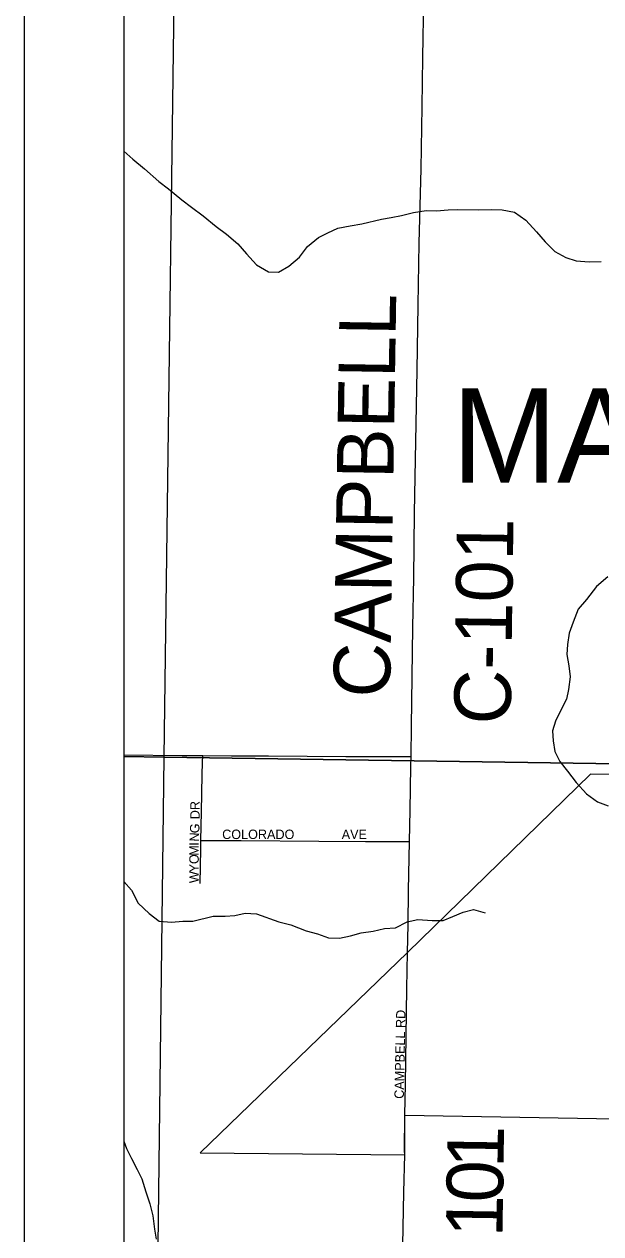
# Model space of a CAD drawing. Extents: x -97 to 34, y -21 to 22.
# Drawn here: x 3.451 to 4.03, y 18.009 to 19.223 of the extents above; entities that cross this region are included whole.
import ezdxf

# ---------------------------------------------------------------- set-up
doc = ezdxf.new("R2010")
doc.units = 0
for name, color, linetype in [('GM_X_City_Street', 7, 'Continuous'), ('GM_X_City_Street_Text', 7, 'Continuous'), ('GM_X_Corporation', 7, 'Continuous'), ('GM_X_Corporation_Text', 7, 'Continuous'), ('GM_X_County_Road', 7, 'Continuous'), ('GM_X_County_Road_Text', 7, 'Continuous'), ('GM_X_Minor_River', 7, 'Continuous'), ('GM_X_Section', 7, 'Continuous'), ('GM_X_Township', 7, 'Continuous'), ('GM_X_Township_Subdivision', 7, 'Continuous'), ('GM_X_Township_Subdivision_Text', 7, 'Continuous'), ('SH_Data', 7, 'Continuous')]:
    doc.layers.add(name, color=color, linetype=linetype)

msp = doc.modelspace()

# ---------------------------------------------------------------- linework, layer by layer
at = {"layer": 'GM_X_City_Street'}
msp.add_lwpolyline([(3.8337, 18.1276), (3.8343, 18.1587), (3.8357, 18.2549), (3.8361, 18.2909)], dxfattribs=at)
at = {"layer": 'GM_X_Corporation'}
msp.add_lwpolyline([(4.2114, 19.235), (4.2125, 18.9803), (4.3454, 18.9792), (4.3427, 18.7167), (4.3419, 18.5845), (4.3404, 18.4802), (4.0889, 18.4887), (4.0886, 18.4691), (4.0199, 18.47), (3.8361, 18.2909), (3.6281, 18.09), (3.8334, 18.0877), (3.8337, 18.1276), (4.0837, 18.1232), (4.0817, 18.0064), (4.155, 18.0631), (4.1841, 18.0856), (4.2719, 18.154), (4.3101, 18.1836), (4.3784, 18.2366), (4.3999, 18.253), (4.3922, 17.9771)], dxfattribs=at)
at = {"layer": 'GM_X_County_Road'}
for points in [[(3.8398, 18.4877), (3.8403, 18.518), (3.8417, 18.6175), (3.8427, 18.6672), (3.8434, 18.7325), (3.8458, 18.8756), (3.847, 18.9409), (3.848, 19.0031), (3.8498, 19.0778), (3.8508, 19.14), (3.8515, 19.1897), (3.8528, 19.2488), (3.8542, 19.311), (3.8551, 19.3732), (3.8564, 19.4417), (3.8568, 19.4697), (3.8564, 19.476), (3.8562, 19.478), (3.8557, 19.4796)], [(3.5515, 18.4893), (3.6099, 18.4889), (3.6308, 18.4887)], [(3.6308, 18.4887), (3.6595, 18.4886), (3.6968, 18.4884), (3.7745, 18.4879), (3.8148, 18.4877), (3.8304, 18.4877), (3.8398, 18.4877)], [(3.8383, 18.4024), (3.8389, 18.434), (3.8396, 18.4776), (3.8398, 18.4877)], [(3.8361, 18.2909), (3.8369, 18.3189), (3.8374, 18.3532), (3.8383, 18.4024)], [(3.8334, 18.0877), (3.8333, 18.092), (3.8337, 18.1276)], [(3.8301, 17.8968), (3.8304, 17.9181), (3.8305, 17.9315), (3.8316, 17.9972), (3.8324, 18.0504), (3.8334, 18.0877)]]:
    msp.add_lwpolyline(points, dxfattribs=at)
at = {"layer": 'GM_X_Minor_River'}
for points in [[(3.5515, 19.0954), (3.5606, 19.0875), (3.5721, 19.0778), (3.5867, 19.065), (3.5964, 19.0576), (3.6098, 19.0468), (3.6195, 19.0394), (3.6311, 19.0305), (3.6441, 19.02), (3.6546, 19.0123), (3.6658, 19.0026), (3.6747, 18.9926), (3.6847, 18.9814), (3.6967, 18.9744), (3.7069, 18.9742), (3.7172, 18.9801), (3.7279, 18.989), (3.7357, 18.9999), (3.7468, 19.0088), (3.7563, 19.0136), (3.7662, 19.0183), (3.7787, 19.0204), (3.7905, 19.0225), (3.8102, 19.0274), (3.8197, 19.0288), (3.8303, 19.0309), (3.8421, 19.0341), (3.855, 19.0361), (3.8652, 19.0356), (3.8769, 19.0365), (3.8867, 19.0371), (3.9072, 19.0367), (3.9208, 19.0369), (3.9313, 19.0367), (3.9438, 19.0342), (3.955, 19.0261), (3.9658, 19.0145), (3.9743, 19.0045), (3.9843, 18.9949), (3.9952, 18.9886), (4.0054, 18.9854), (4.0186, 18.9844), (4.0307, 18.9846)], [(4.0372, 18.6683), (4.0261, 18.6586), (4.016, 18.6455), (4.0075, 18.6358), (4.0024, 18.6226), (3.9984, 18.6117), (3.9967, 18.6003), (3.9962, 18.5901), (3.9983, 18.5787), (3.9996, 18.5677), (3.9979, 18.5552), (3.9958, 18.5454), (3.9896, 18.533), (3.9849, 18.5232), (3.9817, 18.5134), (3.9823, 18.5035), (3.984, 18.4929), (3.9891, 18.4826), (3.9969, 18.4729), (4.0054, 18.4618), (4.0158, 18.4502), (4.027, 18.4421), (4.0376, 18.4381)], [(3.5515, 18.3624), (3.5591, 18.3535), (3.566, 18.3405), (3.5768, 18.33), (3.5869, 18.3223), (3.5994, 18.3213), (3.6107, 18.3226), (3.6206, 18.3225), (3.641, 18.3274), (3.6531, 18.3276), (3.663, 18.3282), (3.6732, 18.3306), (3.6846, 18.3297), (3.7071, 18.3217), (3.7192, 18.3189), (3.7346, 18.3129), (3.7459, 18.3097), (3.7571, 18.3057), (3.7681, 18.3055), (3.7791, 18.3076), (3.7897, 18.3108), (3.8019, 18.3125), (3.8132, 18.315), (3.8242, 18.3159), (3.836, 18.3218), (3.8467, 18.3242), (3.861, 18.3232), (3.872, 18.3231), (3.8819, 18.3271), (3.8921, 18.3314), (3.9024, 18.3343), (3.9141, 18.3307)], [(3.5515, 18.1015), (3.554, 18.0942), (3.5592, 18.0843), (3.565, 18.0732), (3.5694, 18.0636), (3.5734, 18.0507), (3.5777, 18.0388), (3.5805, 18.0266), (3.5822, 18.0133), (3.5839, 18.0031)]]:
    msp.add_lwpolyline(points, dxfattribs=at)
at = {"layer": 'GM_X_Section'}
for p, q in [((3.5515, 19.4744), (3.5515, 18.4878)), ((3.5515, 18.4878), (3.5515, 17.48))]:
    msp.add_line(p, q, dxfattribs=at)
for points in [[(3.5515, 18.4878), (3.5921, 18.4871), (3.6049, 19.4739), (3.5515, 19.4744)], [(3.5515, 17.48), (3.5795, 17.4795), (3.5921, 18.4871), (3.5515, 18.4878)]]:
    msp.add_lwpolyline(points, dxfattribs=at)
for points in [[(3.6049, 19.4739), (4.5986, 19.4785), (4.5956, 18.4723), (3.5921, 18.4871)], [(3.5921, 18.4871), (4.5956, 18.4723), (4.5827, 17.473), (3.5795, 17.4795)]]:
    msp.add_lwpolyline(points, close=True, dxfattribs=at)
at = {"layer": 'GM_X_Township'}
msp.add_lwpolyline([(8.6417, 20.8177), (3.5515, 20.8177), (3.5515, 17.4809)], dxfattribs=at)
at = {"layer": 'GM_X_Township_Subdivision'}
for points in [[(3.6289, 18.4033), (3.6294, 18.4321), (3.6301, 18.4695), (3.6306, 18.4819), (3.6308, 18.4887)], [(3.6282, 18.3602), (3.6287, 18.3948), (3.6289, 18.4033)], [(3.6289, 18.4033), (3.6349, 18.4033), (3.6692, 18.4033), (3.7473, 18.4028), (3.7941, 18.4024), (3.819, 18.4023), (3.8315, 18.4023), (3.8383, 18.4024)]]:
    msp.add_lwpolyline(points, dxfattribs=at)
at = {"layer": 'SH_Data'}
for p, q in [((3.4515, 20.9177), (3.4515, 13.9177)), ((3.5515, 20.8177), (3.5515, 14.0177))]:
    msp.add_line(p, q, dxfattribs=at)

# ---------------------------------------------------------------- texts
at = {"layer": 'GM_X_City_Street_Text'}
msp.add_text('CAMPBELL RD', height=0.00947, rotation=88.8195, dxfattribs=at).set_placement((3.8325, 18.144))
at = {"layer": 'GM_X_Corporation_Text'}
msp.add_text('MARION', height=0.0947, rotation=0, dxfattribs=at).set_placement((3.881, 18.7628))
at = {"layer": 'GM_X_County_Road_Text'}
for s, height, rotation, p in [('CAMPBELL', 0.05682, 89.0967, (3.8186, 18.5467)), ('C-101', 0.05682, 89.1731, (3.9397, 18.5197)), ('1', 0.0568, 89.1635, (3.9326, 18.0745)), ('0', 0.0568, 89.1046, (3.932, 18.0397)), ('1', 0.0568, 89.0807, (3.9315, 18.005))]:
    msp.add_text(s, height=height, rotation=rotation, dxfattribs=at).set_placement(p)
at = {"layer": 'GM_X_Township_Subdivision_Text'}
for s, rotation, p in [('DR', 90, (3.6276, 18.4248)), ('G', 87.1791, (3.6271, 18.4105)), ('COLORADO', 0, (3.6502, 18.4049)), ('AVE', 0, (3.7702, 18.4049)), ('N', 87.7924, (3.6268, 18.4022)), ('I', 89.4319, (3.6267, 18.3981)), ('O', 89.9781, (3.6267, 18.3798)), ('M', 89.9818, (3.6267, 18.3881)), ('Y', 89.9781, (3.6267, 18.3714)), ('W', 89.9832, (3.6267, 18.3606))]:
    msp.add_text(s, height=0.00947, rotation=rotation, dxfattribs=at).set_placement(p)

doc.saveas('drawing.dxf')
